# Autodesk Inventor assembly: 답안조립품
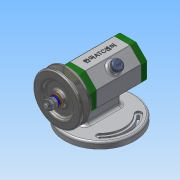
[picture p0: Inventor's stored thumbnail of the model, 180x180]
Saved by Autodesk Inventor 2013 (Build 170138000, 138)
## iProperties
Created: 2017-06
Part Number: 답안조립품
Document SubType Name: Assembly
Designer: Administrator
Author: Administrator
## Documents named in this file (14)
- C:\Users\Administrator\Desktop\470608V1022\답안조립품.iam
- C:\Users\Administrator\Desktop\470608V1022\본체.ipt
- C:\Users\Administrator\Desktop\470608V1022\V벨트풀리.ipt
- C:\Users\Administrator\Desktop\470608V1022\고무캡.ipt
- C:\Users\Administrator\Desktop\470608V1022\너트 M 8.ipt
- C:\Users\Administrator\Desktop\470608V1022\뒤커버.ipt
- C:\Users\Administrator\Desktop\470608V1022\베어링 15 x 32 x 9.ipt
- C:\Users\Administrator\Desktop\470608V1022\볼트 M4 x 12.ipt
- C:\Users\Administrator\Desktop\470608V1022\스프링와셔 8.ipt
- C:\Users\Administrator\Desktop\470608V1022\앞커버.ipt
- C:\Users\Administrator\Desktop\470608V1022\오일 실 15 25 7.ipt
- C:\Users\Administrator\Desktop\470608V1022\와셔 8x17.ipt
- C:\Users\Administrator\Desktop\470608V1022\축.ipt
- C:\Users\Administrator\Desktop\470608V1022\키 3 x 3 x 12.ipt
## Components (2 placed, 2 different names)
1. V벨트풀리:1
2. 고무캡:1
